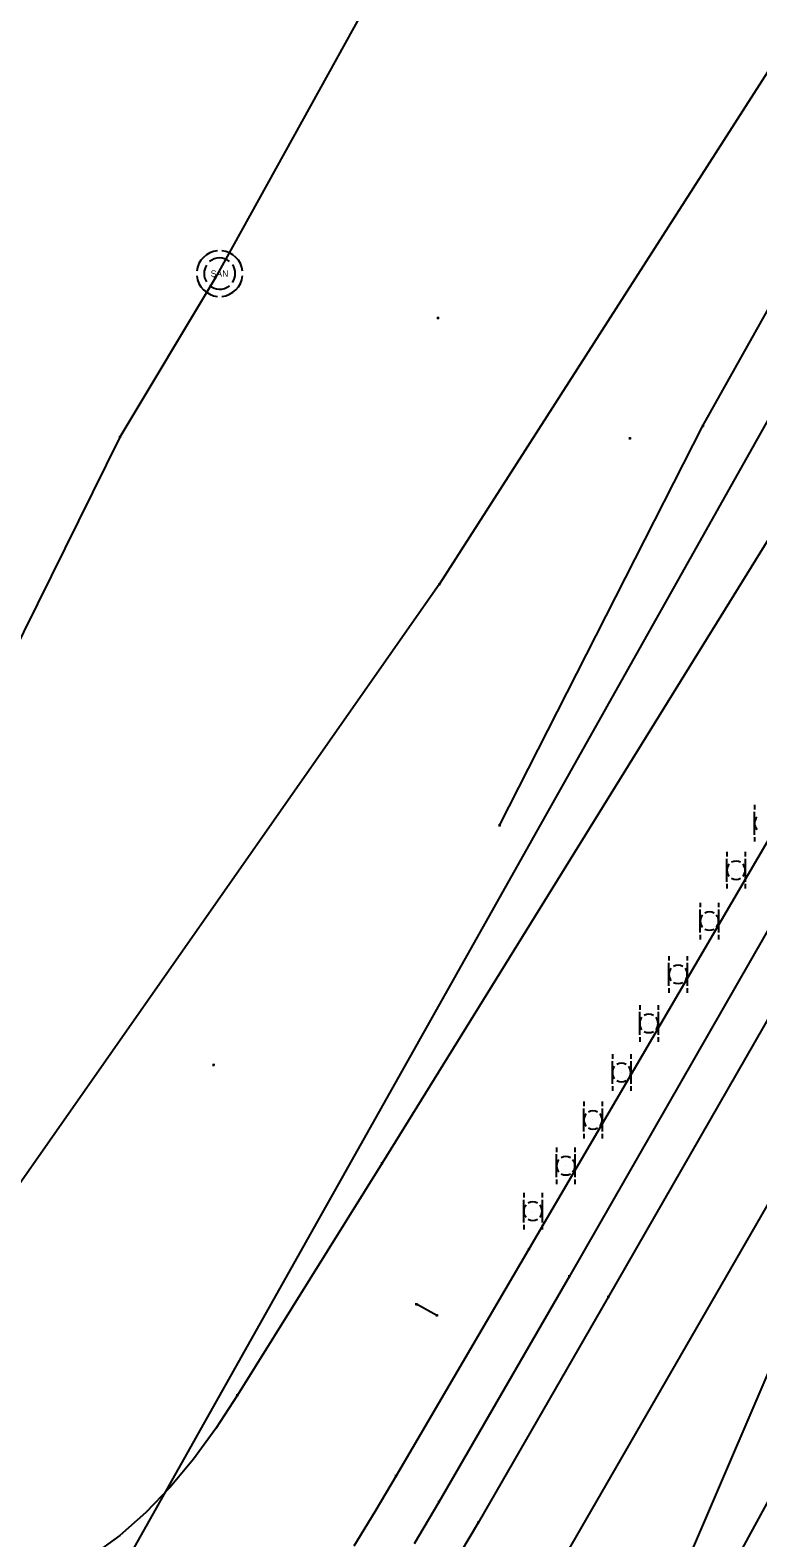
# Model space of a CAD drawing. Extents: x 1954856 to 2011933, y 399149 to 426294.
# Drawn here: x 2006382.8 to 2006462.2, y 401965.3 to 402129.5 of the extents above; entities that cross this region are included whole.
import ezdxf

# ---------------------------------------------------------------- set-up
doc = ezdxf.new("R2010")
doc.units = 0
for name, color, linetype in [('BankMent_ep', 7, 'Continuous'), ('BaselineSurvey', 7, 'Continuous'), ('DelineatorPost_ep', 7, 'Continuous'), ('ManholeSS_ep', 7, 'Continuous'), ('PavtAsphalt_ep', 7, 'Continuous'), ('PMRK_ep', 7, 'Continuous'), ('PointLocator_ep', 7, 'Continuous'), ('SanitaryFM_B_ep', 7, 'Continuous'), ('ShldrPaved_ep', 7, 'Continuous'), ('SignMulti_ep', 7, 'Continuous'), ('WaterA_ep', 7, 'Continuous'), ('WaterNP_B_ep', 7, 'Continuous')]:
    doc.layers.add(name, color=color, linetype=linetype)

msp = doc.modelspace()

# ---------------------------------------------------------------- linework, layer by layer
at = {"layer": 'BankMent_ep'}
for p, q in [((2006478.57, 402067.45), (2006437.2, 401996.74)), ((2006421.19, 402006.12), (2006405.43, 401980.84)), ((2006437.2, 401996.74), (2006422.72, 401972.06))]:
    msp.add_line(p, q, dxfattribs=at)
for points in [[(2006507.44, 402153.57), (2006464.25, 402075.61), (2006421.19, 402006.12)], [(2006405.43, 401980.84), (2006403.06, 401977.23), (2006400.63, 401973.89), (2006398.1, 401970.84), (2006395.44, 401968.06), (2006392.62, 401965.57), (2006389.6, 401963.38)], [(2006422.72, 401972.06), (2006420.4, 401968.15), (2006418.11, 401964.41)]]:
    msp.add_lwpolyline(points, dxfattribs=at)
at = {"layer": 'BaselineSurvey'}
msp.add_lwpolyline([(2006095.1, 401364.22), (2006751.44, 402500.64), (2007687.69, 404121.69)], dxfattribs=at)
at = {"layer": 'DelineatorPost_ep'}
for p, q in [((2006461.78, 402045.13), (2006461.78, 402044.63)), ((2006461.78, 402041.88), (2006461.78, 402044.38)), ((2006461.78, 402041.63), (2006461.78, 402041.13)), ((2006458.77, 402040.02), (2006458.77, 402039.52)), ((2006460.77, 402040.02), (2006460.77, 402039.52)), ((2006458.77, 402036.77), (2006458.77, 402039.27)), ((2006460.77, 402039.27), (2006460.77, 402036.77)), ((2006459.77, 402038.02), (2006459.77, 402038.02)), ((2006458.77, 402036.52), (2006458.77, 402036.02)), ((2006460.77, 402036.52), (2006460.77, 402036.02)), ((2006455.87, 402034.48), (2006455.87, 402033.98)), ((2006455.87, 402031.23), (2006455.87, 402033.73)), ((2006457.87, 402034.48), (2006457.87, 402033.98)), ((2006457.87, 402033.73), (2006457.87, 402031.23)), ((2006456.87, 402032.48), (2006456.87, 402032.48)), ((2006455.87, 402030.98), (2006455.87, 402030.48)), ((2006457.87, 402030.98), (2006457.87, 402030.48)), ((2006452.46, 402028.67), (2006452.46, 402028.17)), ((2006454.46, 402028.67), (2006454.46, 402028.17)), ((2006452.46, 402025.42), (2006452.46, 402027.92)), ((2006454.46, 402027.92), (2006454.46, 402025.42)), ((2006452.46, 402025.17), (2006452.46, 402024.67)), ((2006453.46, 402026.67), (2006453.46, 402026.67)), ((2006454.46, 402025.17), (2006454.46, 402024.67)), ((2006449.27, 402023.33), (2006449.27, 402022.83)), ((2006449.27, 402020.08), (2006449.27, 402022.58)), ((2006451.27, 402023.33), (2006451.27, 402022.83)), ((2006451.27, 402022.58), (2006451.27, 402020.08)), ((2006450.27, 402021.33), (2006450.27, 402021.33)), ((2006449.27, 402019.83), (2006449.27, 402019.33)), ((2006451.27, 402019.83), (2006451.27, 402019.33)), ((2006446.29, 402017.99), (2006446.29, 402017.49)), ((2006446.29, 402014.74), (2006446.29, 402017.24)), ((2006448.29, 402017.99), (2006448.29, 402017.49)), ((2006448.29, 402017.24), (2006448.29, 402014.74)), ((2006447.29, 402015.99), (2006447.29, 402015.99)), ((2006446.29, 402014.49), (2006446.29, 402013.99)), ((2006448.29, 402014.49), (2006448.29, 402013.99)), ((2006443.18, 402012.82), (2006443.18, 402012.32)), ((2006443.18, 402009.57), (2006443.18, 402012.07)), ((2006445.18, 402012.82), (2006445.18, 402012.32)), ((2006445.18, 402012.07), (2006445.18, 402009.57)), ((2006444.18, 402010.82), (2006444.18, 402010.82)), ((2006443.18, 402009.32), (2006443.18, 402008.82)), ((2006445.18, 402009.32), (2006445.18, 402008.82)), ((2006440.21, 402007.83), (2006440.21, 402007.33)), ((2006440.21, 402004.58), (2006440.21, 402007.08)), ((2006442.21, 402007.83), (2006442.21, 402007.33)), ((2006442.21, 402007.08), (2006442.21, 402004.58)), ((2006441.21, 402005.83), (2006441.21, 402005.83)), ((2006440.21, 402004.33), (2006440.21, 402003.83)), ((2006442.21, 402004.33), (2006442.21, 402003.83)), ((2006436.63, 402002.89), (2006436.63, 402002.39)), ((2006436.63, 401999.64), (2006436.63, 402002.14)), ((2006438.63, 402002.89), (2006438.63, 402002.39)), ((2006438.63, 402002.14), (2006438.63, 401999.64)), ((2006437.63, 402000.89), (2006437.63, 402000.89)), ((2006436.63, 401999.39), (2006436.63, 401998.89)), ((2006438.63, 401999.39), (2006438.63, 401998.89))]:
    msp.add_line(p, q, dxfattribs=at)
for centre, start, end in [((2006462.78, 402043.13), 138.5904, 221.4096), ((2006459.77, 402038.02), 138.5904, 221.4096), ((2006459.77, 402038.02), 60, 120), ((2006459.77, 402038.02), 318.5904, 41.4096), ((2006459.77, 402038.02), 240, 300), ((2006456.87, 402032.48), 60, 120), ((2006456.87, 402032.48), 138.5904, 221.4096), ((2006456.87, 402032.48), 240, 300), ((2006456.87, 402032.48), 318.5904, 41.4096), ((2006453.46, 402026.67), 138.5904, 221.4096), ((2006453.46, 402026.67), 60, 120), ((2006453.46, 402026.67), 318.5904, 41.4096), ((2006453.46, 402026.67), 240, 300), ((2006450.27, 402021.33), 138.5904, 221.4096), ((2006450.27, 402021.33), 60, 120), ((2006450.27, 402021.33), 318.5904, 41.4096), ((2006450.27, 402021.33), 240, 300), ((2006447.29, 402015.99), 60, 120), ((2006447.29, 402015.99), 138.5904, 221.4096), ((2006447.29, 402015.99), 318.5904, 41.4096), ((2006447.29, 402015.99), 240, 300), ((2006444.18, 402010.82), 138.5904, 221.4096), ((2006444.18, 402010.82), 60, 120), ((2006444.18, 402010.82), 318.5904, 41.4096), ((2006444.18, 402010.82), 240, 300), ((2006441.21, 402005.83), 138.5904, 221.4096), ((2006441.21, 402005.83), 60, 120), ((2006441.21, 402005.83), 318.5904, 41.4096), ((2006441.21, 402005.83), 240, 300), ((2006437.63, 402000.89), 138.5904, 221.4096), ((2006437.63, 402000.89), 60, 120), ((2006437.63, 402000.89), 318.5904, 41.4096), ((2006437.63, 402000.89), 240, 300)]:
    msp.add_arc(centre, 1, start, end, dxfattribs=at)
at = {"layer": 'ManholeSS_ep'}
msp.add_line((2006403.49, 402102.99), (2006403.49, 402102.99), dxfattribs=at)
for radius, start, end in [(2.5, 95.7392, 174.2608), (1.7, 146.8966, 211.659), (1.7, 51.6487, 129.9836), (2.5, 5.7392, 84.2608), (1.7, 325.7758, 34.7357), (2.5, 185.7392, 264.2608), (2.5, 275.7392, 354.2608), (1.7, 228.572, 308.8628)]:
    msp.add_arc((2006403.49, 402102.99), radius, start, end, dxfattribs=at)
at = {"layer": 'PavtAsphalt_ep'}
for p, q in [((2006486.83, 402062.9), (2006445.85, 401991.54)), ((2006445.85, 401991.54), (2006431.66, 401966.96))]:
    msp.add_line(p, q, dxfattribs=at)
msp.add_lwpolyline([(2006431.66, 401966.96), (2006428.84, 401962.19)], dxfattribs=at)
at = {"layer": 'PMRK_ep'}
msp.add_line((2006454.18, 401962.09), (2006486.86, 402038.25), dxfattribs=at)
msp.add_lwpolyline([(2006391.58, 401838.69), (2006429.54, 401907.47), (2006468, 401977.95), (2006496.74, 402032.18)], dxfattribs=at)
at = {"layer": 'PointLocator_ep'}
for p, q in [((2006403.12, 402102.49), (2006402.87, 402102.49)), ((2006403, 402102.37), (2006403, 402102.62)), ((2006403, 402102.49), (2006403, 402102.49)), ((2006427.42, 402098.15), (2006427.17, 402098.15)), ((2006427.29, 402098.02), (2006427.29, 402098.27)), ((2006427.29, 402098.15), (2006427.29, 402098.15)), ((2006456.29, 402086.4), (2006456.04, 402086.4)), ((2006456.16, 402086.28), (2006456.16, 402086.53)), ((2006456.16, 402086.4), (2006456.16, 402086.4)), ((2006392.74, 402085.16), (2006392.49, 402085.16)), ((2006392.62, 402085.03), (2006392.62, 402085.28)), ((2006392.62, 402085.16), (2006392.62, 402085.16)), ((2006448.34, 402085.04), (2006448.09, 402085.04)), ((2006448.21, 402084.92), (2006448.21, 402085.17)), ((2006448.21, 402085.04), (2006448.21, 402085.04)), ((2006427.55, 402069.13), (2006427.3, 402069.13)), ((2006427.42, 402069.01), (2006427.42, 402069.26)), ((2006427.42, 402069.13), (2006427.42, 402069.13)), ((2006434.12, 402042.9), (2006433.87, 402042.9)), ((2006433.99, 402042.77), (2006433.99, 402043.02)), ((2006433.99, 402042.9), (2006433.99, 402042.9)), ((2006402.83, 402016.68), (2006402.83, 402016.93)), ((2006402.95, 402016.81), (2006402.7, 402016.81)), ((2006402.83, 402016.81), (2006402.83, 402016.81)), ((2006421.32, 402006.12), (2006421.07, 402006.12)), ((2006421.19, 402005.99), (2006421.19, 402006.24)), ((2006421.19, 402006.12), (2006421.19, 402006.12)), ((2006437.32, 401996.74), (2006437.07, 401996.74)), ((2006437.2, 401996.61), (2006437.2, 401996.86)), ((2006437.2, 401996.74), (2006437.2, 401996.74)), ((2006441.61, 401993.67), (2006441.61, 401993.92)), ((2006441.74, 401993.8), (2006441.49, 401993.8)), ((2006441.61, 401993.8), (2006441.61, 401993.8)), ((2006425.06, 401990.75), (2006424.81, 401990.75)), ((2006424.93, 401990.63), (2006424.93, 401990.88)), ((2006424.93, 401990.75), (2006424.93, 401990.75)), ((2006445.98, 401991.54), (2006445.73, 401991.54)), ((2006445.85, 401991.41), (2006445.85, 401991.66)), ((2006445.85, 401991.54), (2006445.85, 401991.54)), ((2006427.29, 401989.54), (2006427.04, 401989.54)), ((2006427.16, 401989.42), (2006427.16, 401989.67)), ((2006427.16, 401989.54), (2006427.16, 401989.54)), ((2006405.55, 401980.84), (2006405.3, 401980.84)), ((2006405.43, 401980.72), (2006405.43, 401980.97)), ((2006405.43, 401980.84), (2006405.43, 401980.84)), ((2006422.84, 401972.06), (2006422.59, 401972.06)), ((2006422.72, 401971.94), (2006422.72, 401972.19)), ((2006422.72, 401972.06), (2006422.72, 401972.06)), ((2006427.37, 401969.08), (2006427.37, 401969.33)), ((2006427.5, 401969.21), (2006427.25, 401969.21)), ((2006427.37, 401969.21), (2006427.37, 401969.21)), ((2006431.79, 401966.96), (2006431.54, 401966.96)), ((2006431.66, 401966.83), (2006431.66, 401967.08)), ((2006431.66, 401966.96), (2006431.66, 401966.96))]:
    msp.add_line(p, q, dxfattribs=at)
at = {"layer": 'SanitaryFM_B_ep'}
for points in [[(2007401.95, 403818.63), (2007312.3, 403645.73), (2007290.75, 403604.1), (2007263.4, 403556.68), (2007243.69, 403523.41), (2007211.46, 403477.24), (2007146.71, 403360.43), (2007074.94, 403233.14), (2007057.11, 403197.22), (2007018.41, 403142.13), (2006986.05, 403110.09), (2006967.4, 403089.86), (2006949.18, 403062), (2006912.39, 403001.77), (2006860.92, 402920.48), (2006691.88, 402620.5), (2006600.9, 402464.44), (2006520.64, 402315.09), (2006403, 402102.49), (2006392.62, 402085.16), (2006366.88, 402033.22), (2006268.08, 401998.8), (2006240.51, 401985.14), (2006227.32, 401976.32)], [(2007078.74, 403198.4), (2007031.79, 403125.31), (2006978.01, 403035.87), (2006927.36, 402959.7), (2006863.76, 402845.21), (2006819, 402760.68), (2006799.33, 402721.33), (2006714.07, 402569.46), (2006673.75, 402500.47), (2006641.55, 402441.62), (2006575.62, 402322.42), (2006531.09, 402244.15), (2006469.22, 402134.35), (2006427.42, 402069.13), (2006371.5, 401989.4)]]:
    msp.add_lwpolyline(points, dxfattribs=at)
at = {"layer": 'ShldrPaved_ep'}
for p, q in [((2006482.52, 402065.14), (2006441.61, 401993.8)), ((2006441.61, 401993.8), (2006427.37, 401969.21))]:
    msp.add_line(p, q, dxfattribs=at)
msp.add_lwpolyline([(2006427.37, 401969.21), (2006424.69, 401964.68)], dxfattribs=at)
at = {"layer": 'SignMulti_ep'}
msp.add_lwpolyline([(2006427.16, 401989.54), (2006424.93, 401990.75)], dxfattribs=at)
at = {"layer": 'WaterA_ep'}
msp.add_lwpolyline([(2007183.71, 403343.35), (2007159.89, 403302.21), (2007091.06, 403185.8), (2007048.72, 403112.53), (2006998.4, 403024.32), (2006953.5, 402944.34), (2006900.79, 402854.48), (2006848.29, 402761.17), (2006824.2, 402718.39), (2006722.16, 402548.68), (2006655.5, 402430.73), (2006588.72, 402313.14), (2006543.83, 402235.68), (2006485.84, 402127.23), (2006385.47, 401948.84)], dxfattribs=at)
at = {"layer": 'WaterNP_B_ep'}
msp.add_lwpolyline([(2006433.99, 402042.9), (2006456.16, 402086.4), (2006478.36, 402126.14), (2006495.22, 402164.8), (2006504.71, 402186.55), (2006528.24, 402222.08), (2006572.35, 402300.58), (2006631.69, 402409.75), (2006664.85, 402468.85), (2006775.08, 402656.4), (2006826.97, 402745.97), (2006874.88, 402831.28), (2006921.38, 402912.75), (2006944.33, 402952.47), (2006965.19, 402991.67), (2007050.42, 403136.24), (2007082.62, 403193.93), (2007116.1, 403252.38), (2007160.14, 403327.81), (2007179.84, 403361.08), (2007198.99, 403394.85)], dxfattribs=at)

# ---------------------------------------------------------------- texts
at = {"layer": 'ManholeSS_ep'}
msp.add_text('SAN', height=0.7, dxfattribs=at).set_placement((2006402.51, 402102.64))

doc.saveas('drawing.dxf')
